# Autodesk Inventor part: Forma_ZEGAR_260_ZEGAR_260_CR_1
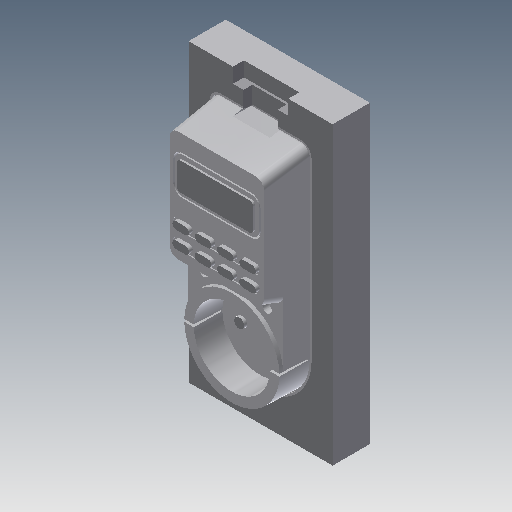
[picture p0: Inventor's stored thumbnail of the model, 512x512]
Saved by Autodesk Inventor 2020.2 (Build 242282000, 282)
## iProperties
Created: 2015-01
Part Number: Forma_ZEGAR_260_ZEGAR_260_CR_1
Material: Ogólny
Document SubType Name: Modeling
Designer: F.Stasiak
Density: 1 g/cm^3
Appearance: Domyślna
Catalog Web Link: www.expertbooks.pl
Manager: www.cadconsulting.pl
Company: Fabian Stasiak CAD Consulting
Author: F.Stasiak
Subject: Zbiór ćwiczeń. Autodesk Inventor 2020. Kurs Professional
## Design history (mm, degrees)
node "Forma_ZEGAR_260_ZEGAR_260_CR_Base"
feature "Bryła5::Forma_ZEGAR_260_ZEGAR_260_CR_Base"
tag "Bryła wyprowadzona5"
node "Bryła5"
feature "Forma_ZEGAR_260_ZEGAR_260_CR_Base_Bodies"
